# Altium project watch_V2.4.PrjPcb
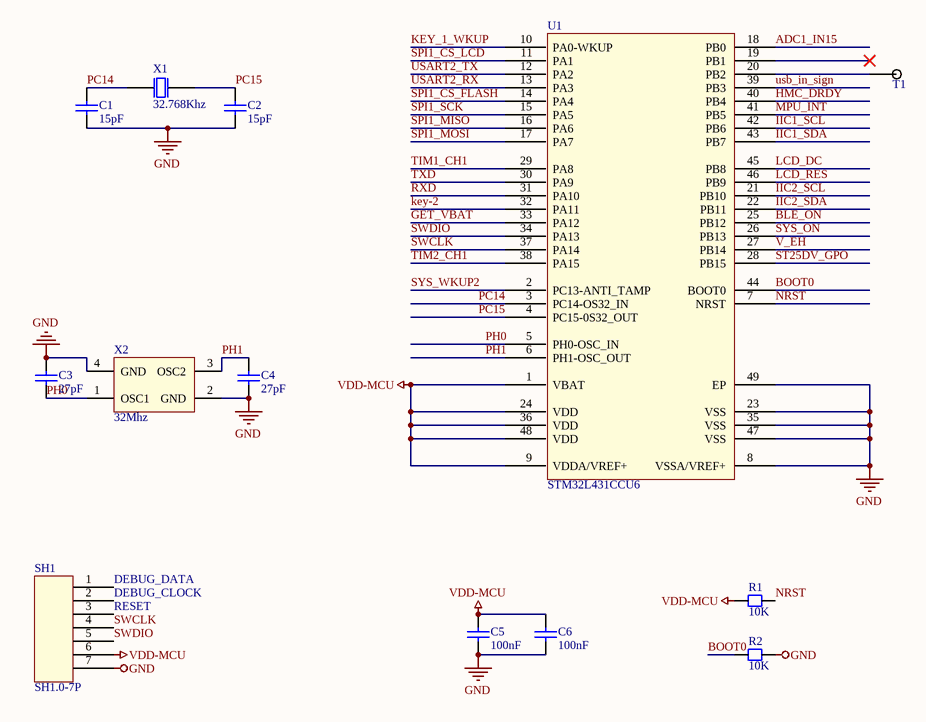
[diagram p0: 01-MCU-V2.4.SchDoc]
4 sheets, 95 parts. Net scope: global (net labels, ports and power ports of the same name join across sheets).
Board file: PCB-watch-V2.4.PcbDoc
Sheets:
  01-MCU-V2.4.SchDoc
  02-bluetooth-V2.4.SchDoc
  03-PeripheralPart-V2.4.SchDoc
  04-POWERV2.4.SchDoc

## Sheet 01-MCU-V2.4.SchDoc
size A4; Organization: Protel International P/L; Address1: L3, 12a Rodborough Rd; Address2: Frenchs Forest; Address3: NSW; Address4: Australia 2086

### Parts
C1  15pF  [CC1005-0402]
C2  15pF  [CC1005-0402]
C3  27pF  [CC1005-0402]
C4  27pF  [CC1005-0402]
C5  100nF  [CC1005-0402]
C6  100nF  [CC1005-0402]
R1  10K  [CR1005-0402]
R2  10K  [CR1005-0402]
SH1  SH1.0-7P  [SH1.0-7P]
T1  测试点  [测试点]  (value not drawn)
U1  STM32L431CCU6  [STM32-UFQFPN48_N]
X1  32.768Khz  [XTAL-2012]
X2  32Mhz  [XTAL-2016]

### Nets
GND: C1.1 C2.1 C3.2 C4.1 C5.1 C6.1 R2.1 SH1.7 U1.8(VSSA/VREF+) U1.23(VSS) U1.35(VSS) U1.47(VSS) U1.49(EP) X2.2(GND) X2.4(GND)
VDD-MCU: C5.2 C6.2 R1.2 SH1.6 U1.1(VBAT) U1.9(VDDA/VREF+) U1.24(VDD) U1.36(VDD) U1.48(VDD)
ADC1_IN15: U1.18(PB0)
BLE_ON: U1.25(PB12)
BOOT0: R2.2 U1.44(BOOT0)
DEBUG_CLOCK: SH1.2
DEBUG_DATA: SH1.1
GET_VBAT: U1.33(PA12)
HMC_DRDY: U1.40(PB4)
IIC1_SCL: U1.42(PB6)
IIC1_SDA: U1.43(PB7)
IIC2_SCL: U1.21(PB10)
IIC2_SDA: U1.22(PB11)
key-2: U1.32(PA11)
KEY_1_WKUP: U1.10(PA0-WKUP)
LCD_DC: U1.45(PB8)
LCD_RES: U1.46(PB9)
MPU_INT: U1.41(PB5)
NRST: R1.1 U1.7(NRST)
PC14: C1.2 U1.3(PC14-OS32_IN) X1.2
PC15: C2.2 U1.4(PC15-0S32_OUT) X1.1
PH0: C3.1 U1.5(PH0-OSC_IN) X2.1(OSC1)
PH1: C4.2 U1.6(PH1-OSC_OUT) X2.3(OSC2)
RESET: SH1.3
RXD: U1.31(PA10)
SPI1_CS_FLASH: U1.14(PA4)
SPI1_CS_LCD: U1.11(PA1)
SPI1_MISO: U1.16(PA6)
SPI1_MOSI: U1.17(PA7)
SPI1_SCK: U1.15(PA5)
ST25DV_GPO: U1.28(PB15)
SWCLK: SH1.4 U1.37(PA14)
SWDIO: SH1.5 U1.34(PA13)
SYS_ON: U1.26(PB13)
SYS_WKUP2: U1.2(PC13-ANTI_TAMP)
TIM1_CH1: U1.29(PA8)
TIM2_CH1: U1.38(PA15)
TXD: U1.30(PA9)
USART2_RX: U1.13(PA3)
USART2_TX: U1.12(PA2)
usb_in_sign: U1.39(PB3)
V_EH: U1.27(PB14)
NetT1_1: T1.1 U1.20(PB2)

Not connected (* = marked no-connect by the designer): U1 19(PB1)*

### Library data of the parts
C1-C6 = Chip capacitor: 贴片电容
R1 R2 = Chip resistor: 贴片电阻
SH1 = SH1.0-7P: 间距为1mm的端子
U1 = STM32L431CCU6: stm32低功耗单片机 主频80MHz
X1 = XTAL 2012: 2012封装的时钟晶振
X2 = XTAL 2016: 2016封装的晶振

## Sheet 02-bluetooth-V2.4.SchDoc
size A4; Organization: Protel International P/L; Address1: L3, 12a Rodborough Rd; Address2: Frenchs Forest; Address3: NSW; Address4: Australia 2086
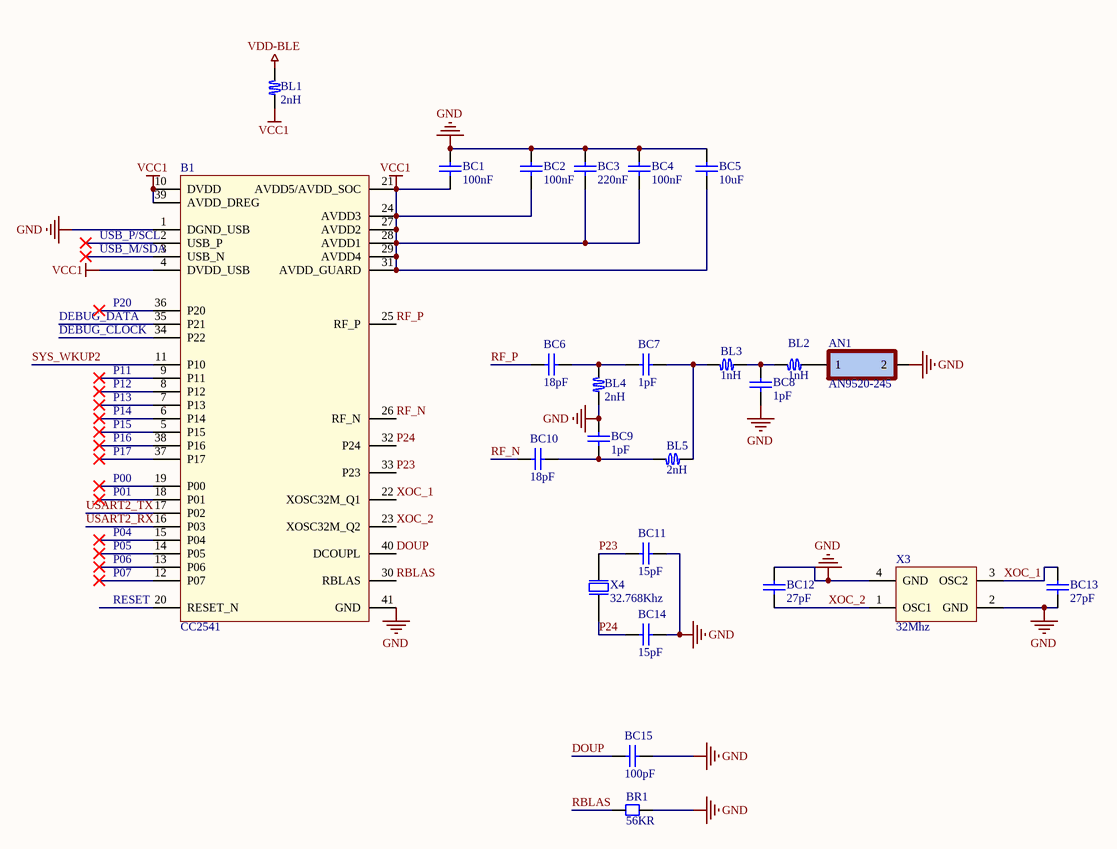
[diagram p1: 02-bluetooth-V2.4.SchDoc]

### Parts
AN1  AN9520-245  [AN-5120]
B1  CC2541  [QFN40-CC254X]
BC1  100nF  [CC1005-0402]
BC2  100nF  [CC1005-0402]
BC3  220nF  [CC1005-0402]
BC4  100nF  [CC1005-0402]
BC5  10uF  [CC1005-0402]
BC6  18pF  [CC1005-0402]
BC7  1pF  [CC1005-0402]
BC8  1pF  [CC1005-0402]
BC9  1pF  [CC1005-0402]
BC10  18pF  [CC1005-0402]
BC11  15pF  [CC1005-0402]
BC12  27pF  [CC1005-0402]
BC13  27pF  [CC1005-0402]
BC14  15pF  [CC1005-0402]
BC15  100pF  [CC1005-0402]
BL1  2nH  [Inductor-0402]
BL2  1nH  [Inductor-0402]
BL3  1nH  [Inductor-0402]
BL4  2nH  [Inductor-0402]
BL5  2nH  [Inductor-0402]
BR1  56KR  [CR1005-0402]
X3  32Mhz  [XTAL-2016]
X4  32.768Khz  [XTAL-2012]

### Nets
GND: AN1.2 B1.1(DGND_USB) B1.41(GND) BC1.2 BC2.2 BC3.2 BC4.2 BC5.2 BC8.1 BC9.1 BC11.2 BC12.2 BC13.1 BC14.2 BC15.1 BL4.1 BR1.2 X3.2(GND) X3.4(GND)
VCC1: B1.4(DVDD_USB) B1.10(DVDD) B1.21(AVDD5/AVDD_SOC) B1.24(AVDD3) B1.27(AVDD2) B1.28(AVDD1) B1.29(AVDD4) B1.31(AVDD_GUARD) B1.39(AVDD_DREG) BC1.1 BC2.1 BC3.1 BC4.1 BC5.1 BL1.1
VDD-BLE: BL1.2
DEBUG_CLOCK: B1.34(P22)
DEBUG_DATA: B1.35(P21)
DOUP: B1.40(DCOUPL) BC15.2
P00: B1.19(P00)
P01: B1.18(P01)
P04: B1.15(P04)
P05: B1.14(P05)
P06: B1.13(P06)
P07: B1.12(P07)
P11: B1.9(P11)
P12: B1.8(P12)
P13: B1.7(P13)
P14: B1.6(P14)
P15: B1.5(P15)
P16: B1.38(P16)
P17: B1.37(P17)
P20: B1.36(P20)
P23: B1.33(P23) BC11.1 X4.2
P24: B1.32(P24) BC14.1 X4.1
RBLAS: B1.30(RBLAS) BR1.1
RESET: B1.20(RESET_N)
RF_N: B1.26(RF_N) BC10.2
RF_P: B1.25(RF_P) BC6.2
SYS_WKUP2: B1.11(P10)
USART2_RX: B1.16(P03)
USART2_TX: B1.17(P02)
USB_M/SDA: B1.3(USB_N)
USB_P/SCL: B1.2(USB_P)
XOC_1: B1.22(XOSC32M_Q1) BC13.2 X3.3(OSC2)
XOC_2: B1.23(XOSC32M_Q2) BC12.1 X3.1(OSC1)
NetAN1_1: AN1.1 BL2.1
NetBC6_1: BC6.1 BC7.1 BL4.2
NetBC7_2: BC7.2 BL3.2 BL5.1
NetBC8_2: BC8.2 BL2.2 BL3.1
NetBC9_2: BC9.2 BC10.1 BL5.2

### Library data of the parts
AN1 = AN9520-245: 2.4G全向天线 蓝牙天线 陶瓷贴片 WIFI内置
B1 = CC2541: 低功耗蓝牙芯片
BC1-BC15 = Chip capacitor: 贴片电容
BL1-BL5 = Inductor-0402: 0402封装的电感
BR1 = Chip resistor: 贴片电阻
X3 = XTAL 2016: 2016封装的晶振
X4 = XTAL 2012: 2012封装的时钟晶振

## Sheet 03-PeripheralPart-V2.4.SchDoc
size A4
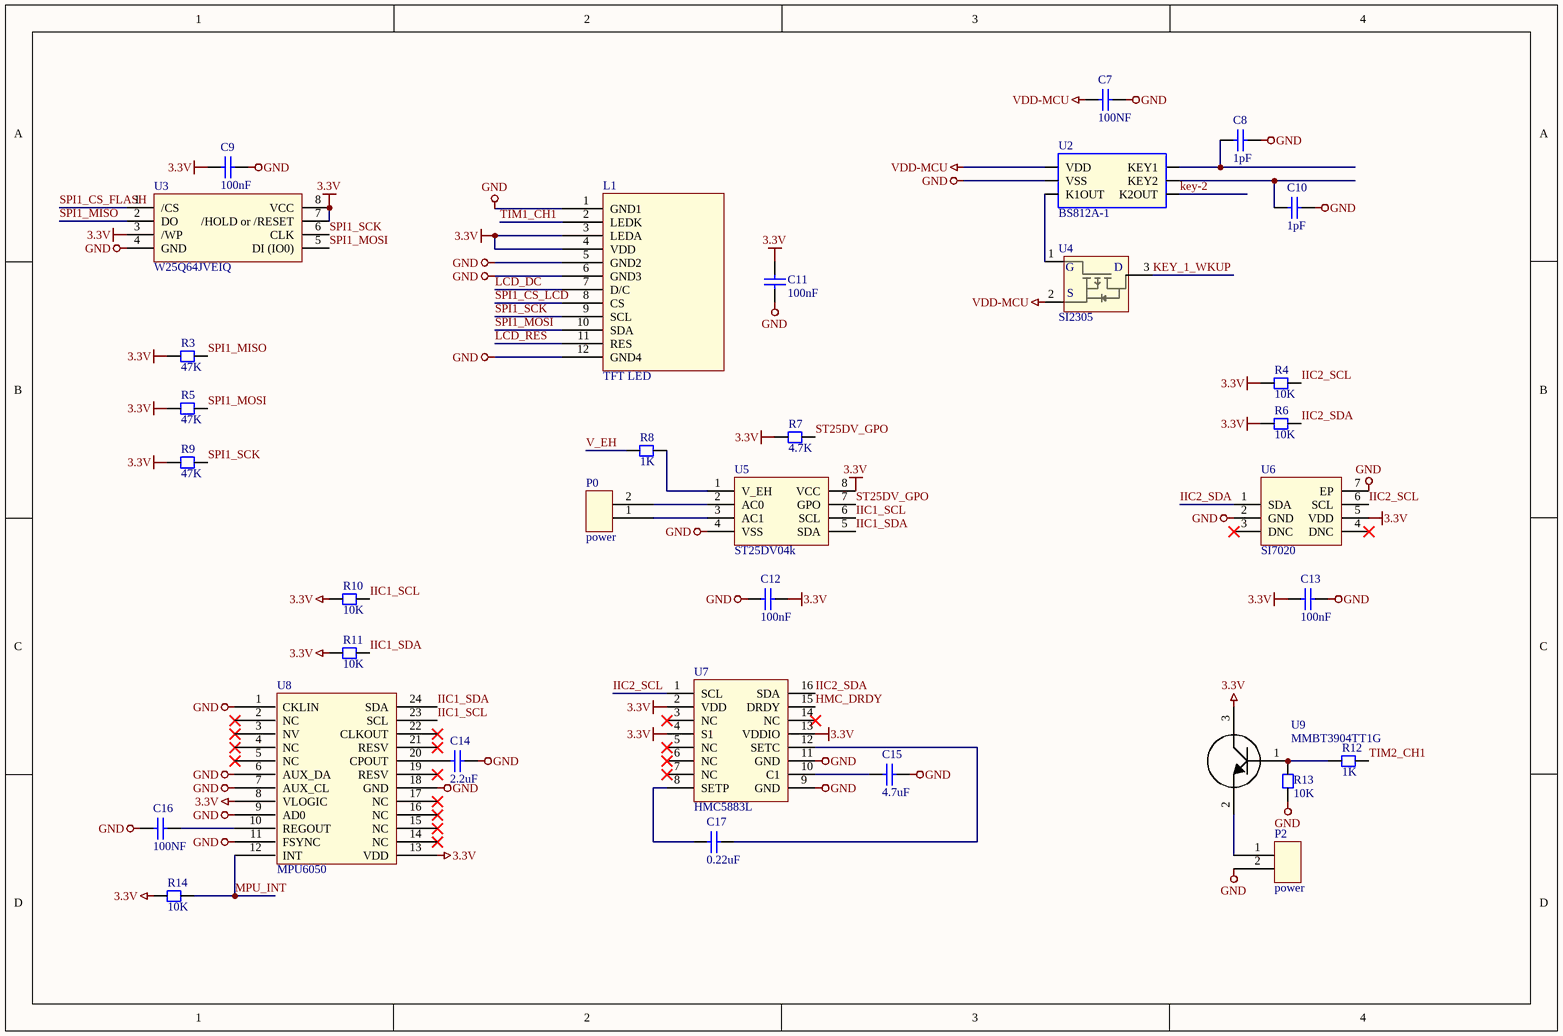
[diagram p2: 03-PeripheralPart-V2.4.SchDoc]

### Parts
C7  100NF  [CC1005-0402]
C8  1pF  [CC1005-0402]
C9  100nF  [CC1005-0402]
C10  1pF  [CC1005-0402]
C11  100nF  [CC1005-0402]
C12  100nF  [CC1005-0402]
C13  100nF  [CC1005-0402]
C14  2.2uF  [CC1005-0402]
C15  4.7uF  [CC1005-0402]
C16  100NF  [CC1005-0402]
C17  0.22uF  [CC1005-0402]
L1  TFT LED  [LCD-1.3-(2)]
P0  power  [POWER2]
P2  power  [POWER-3.7V]
R3  47K  [CR1005-0402]
R4  10K  [CR1005-0402]
R5  47K  [CR1005-0402]
R6  10K  [CR1005-0402]
R7  4.7K  [CR1005-0402]
R8  1K  [CR1005-0402]
R9  47K  [CR1005-0402]
R10  10K  [CR1005-0402]
R11  10K  [CR1005-0402]
R12  1K  [CR1005-0402]
R13  10K  [CR1005-0402]
R14  10K  [CR1005-0402]
U2  BS812A-1  [SOT23-6]
U3  W25Q64JVEIQ  [WSON-8_L8.0-W6.10-P1.27-TL-EP]
U4  SI2305  [SOT-23]
U5  ST25DV04k  [UFDFPN8]
U6  SI7020  [DFN-6]
U7  HMC5883L  [LPCC-16_L3.0-W3.0-P0.50-BL]
U8  MPU6050  [QFN24 - duplicate]
U9  MMBT3904TT1G  [SOT-416]

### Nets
3.3V: C9.1 C11.1 C12.2 C13.1 L1.3(LEDA) L1.4(VDD) R3.2 R4.2 R5.2 R6.2 R7.1 R9.2 R10.2 R11.2 R14.2 U3.3(/WP) U3.7(/HOLD_or_/RESET) U3.8(VCC) U5.8(VCC) U6.5(VDD) U7.2(VDD) U7.4(S1) U7.13(VDDIO) U8.8(VLOGIC) U8.13(VDD) U9.3
GND: C7.1 C8.2 C9.2 C10.2 C11.2 C12.1 C13.2 C14.2 C15.2 C16.1 L1.1(GND1) L1.5(GND2) L1.6(GND3) L1.12(GND4) P2.2 R13.2 U2.2(VSS) U3.4(GND) U5.4(VSS) U6.2(GND) U6.7(EP) U7.9(GND) U7.11(GND) U8.1(CKLIN) U8.6(AUX_DA) U8.7(AUX_CL) U8.9(AD0) U8.11(FSYNC) U8.18(GND)
VDD-MCU: C7.2 U2.1(VDD) U4.2(SOURCE)
HMC_DRDY: U7.15(DRDY)
IIC1_SCL: R10.1 U5.6(SCL) U8.23(SCL)
IIC1_SDA: R11.1 U5.5(SDA) U8.24(SDA)
IIC2_SCL: R4.1 U6.6(SCL) U7.1(SCL)
IIC2_SDA: R6.1 U6.1(SDA) U7.16(SDA)
key-2: U2.4(K2OUT)
KEY_1_WKUP: U4.3(DRAIN)
LCD_DC: L1.7(D/C)
LCD_RES: L1.11(RES)
MPU_INT: R14.1 U8.12(INT)
SPI1_CS_FLASH: U3.1(/CS)
SPI1_CS_LCD: L1.8(CS)
SPI1_MISO: R3.1 U3.2(DO)
SPI1_MOSI: L1.10(SDA) R5.1 U3.5(DI_(IO0))
SPI1_SCK: L1.9(SCL) R9.1 U3.6(CLK)
ST25DV_GPO: R7.2 U5.7(GPO)
TIM1_CH1: L1.2(LEDK)
TIM2_CH1: R12.1
V_EH: R8.2
NetC8_1: C8.1 U2.6(KEY1)
NetC10_1: C10.1 U2.5(KEY2)
NetC14_1: C14.1 U8.20(CPOUT)
NetC15_1: C15.1 U7.10(C1)
NetC16_2: C16.2 U8.10(REGOUT)
NetC17_1: C17.1 U7.8(SETP)
NetC17_2: C17.2 U7.12(SETC)
NetP0_1: P0.1 U5.3(AC1)
NetP0_2: P0.2 U5.2(AC0)
NetP2_1: P2.1 U9.2
NetR8_1: R8.1 U5.1(V_EH)
NetR12_2: R12.2 R13.1 U9.1
NetU2_3: U2.3(K1OUT) U4.1(GATE)

Not connected (* = marked no-connect by the designer): U6 3(DNC)* 4(DNC)*; U7 3(NC)* 5(NC)* 6(NC)* 7(NC)* 14(NC)*; U8 2(NC)* 3(NV)* 4(NC)* 5(NC)* 14(NC)* 15(NC)* 16(NC)* 17(NC)* 19(RESV)* 21(RESV)* 22(CLKOUT)*

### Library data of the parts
C7-C17 = Chip capacitor: 贴片电容
L1 = LCD-IPSscreen-1.3: 1.3寸显示屏幕
R3-R14 = Chip resistor: 贴片电阻
U2 = BS812A-1: 触摸按键 两路 SOP23-6封装极简电路
U3 = W25Q256JVEIQ: FLASH
U4 = SI2305: PMOS场效应MOS管 SOT-23
U5 = ST25DV04k: NFC芯片4K存储空间
U6 = SI7020: 温湿度传感器芯片
U7 = HMC5883L: 三轴罗盘
U8 = MPU6050: 陀螺仪
U9 = MMBT3904TT1G: NPN 电流 - 集电极（Ic）（最大值）：200mA 电压 - 集射极击穿（最大值）：40V SOT-23-3

## Sheet 04-POWERV2.4.SchDoc
size A4
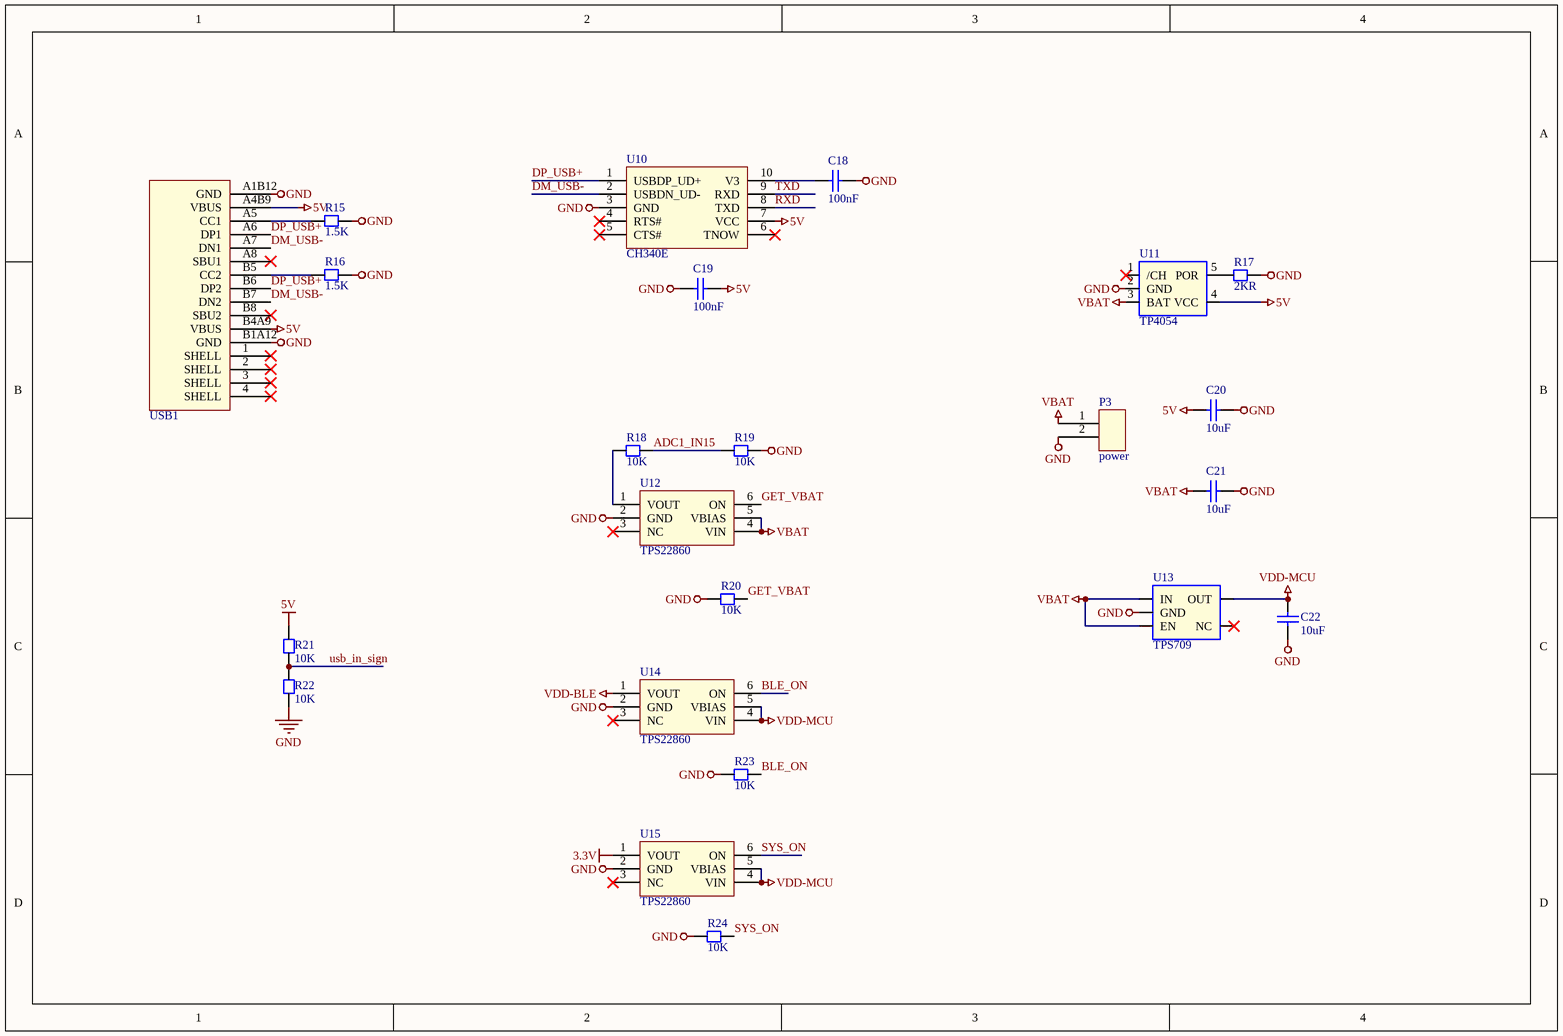
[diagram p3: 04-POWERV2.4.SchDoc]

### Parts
C18  100nF  [CC1005-0402]
C19  100nF  [CC1005-0402]
C20  10uF  [CC1005-0402]
C21  10uF  [CC1005-0402]
C22  10uF  [CC1005-0402]
P3  power  [POWER-3.7V]
R15  1.5K  [CR1005-0402]
R16  1.5K  [CR1005-0402]
R17  2KR  [CR1005-0402]
R18  10K  [CR1005-0402]
R19  10K  [CR1005-0402]
R20  10K  [CR1005-0402]
R21  10K  [CR1005-0402]
R22  10K  [CR1005-0402]
R23  10K  [CR1005-0402]
R24  10K  [CR1005-0402]
U10  CH340E  [MSOP-10]
U11  TP4054  [SOT23-5]
U12  TPS22860  [SOT23-6]
U13  TPS709  [SOT23-5]
U14  TPS22860  [SOT23-6]
U15  TPS22860  [SOT23-6]
USB1  Tpye-c 16P  [TYPE-C 16P]  (value not drawn)

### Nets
3.3V: U15.1(VOUT)
5V: C19.2 C20.2 R21.1 U10.7(VCC) U11.4(VCC) USB1.A4B9(VBUS) USB1.B4A9(VBUS)
GND: C18.2 C19.1 C20.1 C21.1 C22.2 P3.2 R15.1 R16.1 R17.1 R19.2 R20.1 R22.2 R23.1 R24.1 U10.3(GND) U11.2(GND) U12.2(GND) U13.2(GND) U14.2(GND) U15.2(GND) USB1.A1B12(GND) USB1.B1A12(GND)
VBAT: C21.2 P3.1 U11.3(BAT) U12.4(VIN) U12.5(VBIAS) U13.1(IN) U13.3(EN)
VDD-BLE: U14.1(VOUT)
VDD-MCU: C22.1 U13.5(OUT) U14.4(VIN) U14.5(VBIAS) U15.4(VIN) U15.5(VBIAS)
ADC1_IN15: R18.1 R19.1
BLE_ON: R23.2 U14.6(ON)
DM_USB-: U10.2(USBDN_UD-) USB1.A7(DN1) USB1.B7(DN2)
DP_USB+: U10.1(USBDP_UD+) USB1.A6(DP1) USB1.B6(DP2)
GET_VBAT: R20.2 U12.6(ON)
RXD: U10.8(TXD)
SYS_ON: R24.2 U15.6(ON)
TXD: U10.9(RXD)
usb_in_sign: R21.2 R22.1
NetC18_1: C18.1 U10.10(V3)
NetR15_2: R15.2 USB1.A5(CC1)
NetR16_2: R16.2 USB1.B5(CC2)
NetR17_2: R17.2 U11.5(POR)
NetR18_2: R18.2 U12.1(VOUT)

Not connected (* = marked no-connect by the designer): U10 4(RTS#)* 5(CTS#)* 6(TNOW)*; U11 1(/CH)*; U12 3(NC)*; U13 4(NC)*; U14 3(NC)*; U15 3(NC)*; USB1 1(SHELL)* 2(SHELL)* 3(SHELL)* 4(SHELL)* A8(SBU1)* B8(SBU2)*

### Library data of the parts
C18-C22 = Chip capacitor: 贴片电容
R15-R24 = Chip resistor: 贴片电阻
U10 = CH340E: usd转串口芯片 MSOP10封装
U11 = TP4054: 迷你充电IC SOT-23-5
U12 U14 U15 = TPS22860: 超低泄漏电流负载开关  超低泄漏电流负载开关 它可支持最大 200mA 的持续电 / 流。 此开关可由一个打开/关闭输入 (ON) 控制
U13 = TPS709: 3.3V降压IC SOT23-5封装 最大输出150ma电流
USB1 = Tpye-c 16P: 16P 封装的TYPE -c接口 4固定插脚 双向

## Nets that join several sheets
3.3V: 03-PeripheralPart-V2.4 (26 pins), 04-POWERV2.4 (U15.1)
GND: 01-MCU-V2.4 (15 pins), 02-bluetooth-V2.4 (19 pins), 03-PeripheralPart-V2.4 (29 pins), 04-POWERV2.4 (22 pins)
VDD-BLE: 02-bluetooth-V2.4 (BL1.2), 04-POWERV2.4 (U14.1)
VDD-MCU: 01-MCU-V2.4 (9 pins), 03-PeripheralPart-V2.4 (C7.2 U2.1 U4.2), 04-POWERV2.4 (6 pins)
ADC1_IN15: 01-MCU-V2.4 (U1.18), 04-POWERV2.4 (R18.1 R19.1)
BLE_ON: 01-MCU-V2.4 (U1.25), 04-POWERV2.4 (R23.2 U14.6)
DEBUG_CLOCK: 01-MCU-V2.4 (SH1.2), 02-bluetooth-V2.4 (B1.34)
DEBUG_DATA: 01-MCU-V2.4 (SH1.1), 02-bluetooth-V2.4 (B1.35)
GET_VBAT: 01-MCU-V2.4 (U1.33), 04-POWERV2.4 (R20.2 U12.6)
HMC_DRDY: 01-MCU-V2.4 (U1.40), 03-PeripheralPart-V2.4 (U7.15)
IIC1_SCL: 01-MCU-V2.4 (U1.42), 03-PeripheralPart-V2.4 (R10.1 U5.6 U8.23)
IIC1_SDA: 01-MCU-V2.4 (U1.43), 03-PeripheralPart-V2.4 (R11.1 U5.5 U8.24)
IIC2_SCL: 01-MCU-V2.4 (U1.21), 03-PeripheralPart-V2.4 (R4.1 U6.6 U7.1)
IIC2_SDA: 01-MCU-V2.4 (U1.22), 03-PeripheralPart-V2.4 (R6.1 U6.1 U7.16)
key-2: 01-MCU-V2.4 (U1.32), 03-PeripheralPart-V2.4 (U2.4)
KEY_1_WKUP: 01-MCU-V2.4 (U1.10), 03-PeripheralPart-V2.4 (U4.3)
LCD_DC: 01-MCU-V2.4 (U1.45), 03-PeripheralPart-V2.4 (L1.7)
LCD_RES: 01-MCU-V2.4 (U1.46), 03-PeripheralPart-V2.4 (L1.11)
MPU_INT: 01-MCU-V2.4 (U1.41), 03-PeripheralPart-V2.4 (R14.1 U8.12)
RESET: 01-MCU-V2.4 (SH1.3), 02-bluetooth-V2.4 (B1.20)
RXD: 01-MCU-V2.4 (U1.31), 04-POWERV2.4 (U10.8)
SPI1_CS_FLASH: 01-MCU-V2.4 (U1.14), 03-PeripheralPart-V2.4 (U3.1)
SPI1_CS_LCD: 01-MCU-V2.4 (U1.11), 03-PeripheralPart-V2.4 (L1.8)
SPI1_MISO: 01-MCU-V2.4 (U1.16), 03-PeripheralPart-V2.4 (R3.1 U3.2)
SPI1_MOSI: 01-MCU-V2.4 (U1.17), 03-PeripheralPart-V2.4 (L1.10 R5.1 U3.5)
SPI1_SCK: 01-MCU-V2.4 (U1.15), 03-PeripheralPart-V2.4 (L1.9 R9.1 U3.6)
ST25DV_GPO: 01-MCU-V2.4 (U1.28), 03-PeripheralPart-V2.4 (R7.2 U5.7)
SYS_ON: 01-MCU-V2.4 (U1.26), 04-POWERV2.4 (R24.2 U15.6)
SYS_WKUP2: 01-MCU-V2.4 (U1.2), 02-bluetooth-V2.4 (B1.11)
TIM1_CH1: 01-MCU-V2.4 (U1.29), 03-PeripheralPart-V2.4 (L1.2)
TIM2_CH1: 01-MCU-V2.4 (U1.38), 03-PeripheralPart-V2.4 (R12.1)
TXD: 01-MCU-V2.4 (U1.30), 04-POWERV2.4 (U10.9)
USART2_RX: 01-MCU-V2.4 (U1.13), 02-bluetooth-V2.4 (B1.16)
USART2_TX: 01-MCU-V2.4 (U1.12), 02-bluetooth-V2.4 (B1.17)
usb_in_sign: 01-MCU-V2.4 (U1.39), 04-POWERV2.4 (R21.2 R22.1)
V_EH: 01-MCU-V2.4 (U1.27), 03-PeripheralPart-V2.4 (R8.2)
